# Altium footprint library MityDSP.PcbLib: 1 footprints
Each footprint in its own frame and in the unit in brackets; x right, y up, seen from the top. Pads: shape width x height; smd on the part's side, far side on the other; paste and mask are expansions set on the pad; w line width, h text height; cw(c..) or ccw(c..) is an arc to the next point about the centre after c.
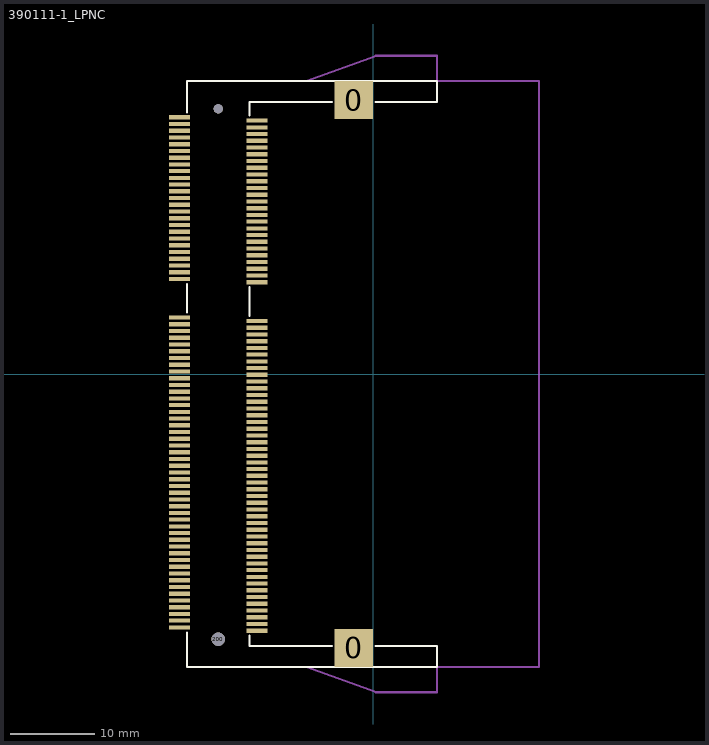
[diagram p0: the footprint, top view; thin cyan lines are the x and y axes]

## 390111-1_LPNC [mm] "MityDSP Socket No Clip"
height 5.6
pads (148):
  rect 4.6x4.5 smd: 0(-2.284,-32.55) 0(-2.284,32.55)
  rect 2.5x0.5 smd: 1(-22.981,30.5) 2(-13.781,30.1) 3(-22.981,29.7) 4(-13.781,29.3) 5(-22.981,28.9) 6(-13.781,28.5) 7(-22.981,28.1) 8(-13.781,27.7) 9(-22.981,27.3) 10(-13.781,26.9) 11(-22.981,26.5) 12(-13.781,26.1) 13(-22.981,25.7) 14(-13.781,25.3) 15(-22.981,24.9) 16(-13.781,24.5) 17(-22.981,24.1) 18(-13.781,23.7) 19(-22.981,23.3) 20(-13.781,22.9) 21(-22.981,22.5) 22(-13.781,22.1) 23(-22.981,21.7) 24(-13.781,21.3) 25(-22.981,20.9) 26(-13.781,20.5) 27(-22.981,20.1) 28(-13.781,19.7) 29(-22.981,19.3) 30(-13.781,18.9) 31(-22.981,18.5) 32(-13.781,18.1) 33(-22.981,17.7) 34(-13.781,17.3) 35(-22.981,16.9) 36(-13.781,16.5) 37(-22.981,16.1) 38(-13.781,15.7) 39(-22.981,15.3) 40(-13.781,14.9) 41(-22.981,14.5) 42(-13.781,14.1) 43(-22.981,13.7) 44(-13.781,13.3) 45(-22.981,12.9) 46(-13.781,12.5) 47(-22.981,12.1) 48(-13.781,11.7) 49(-22.981,11.3) 50(-13.781,10.9) 51(-22.981,6.7) 52(-13.781,6.3) 53(-22.981,5.9) 54(-13.781,5.5) 55(-22.981,5.1) 56(-13.781,4.7) 57(-22.981,4.3) 58(-13.781,3.9) 59(-22.981,3.5) 60(-13.781,3.1) 61(-22.981,2.7) 62(-13.781,2.3) 63(-22.981,1.9) 64(-13.781,1.5) 65(-22.981,1.1) 66(-13.781,0.7) 67(-22.981,0.3) 68(-13.781,-0.1) 69(-22.981,-0.5) 70(-13.781,-0.9) 71(-22.981,-1.3) 72(-13.781,-1.7) 73(-22.981,-2.1) 74(-13.781,-2.5) 75(-22.981,-2.9) 76(-13.781,-3.3) 77(-22.981,-3.7) 78(-13.781,-4.1) 79(-22.981,-4.5) 80(-13.781,-4.9) 81(-22.981,-5.3) 82(-13.781,-5.7) 83(-22.981,-6.1) 84(-13.781,-6.5) 85(-22.981,-6.9) 86(-13.781,-7.3) 87(-22.981,-7.7) 88(-13.781,-8.1) 89(-22.981,-8.5) 90(-13.781,-8.9) 91(-22.981,-9.3) 92(-13.781,-9.7) 93(-22.981,-10.1) 94(-13.781,-10.5) 95(-22.981,-10.9) 96(-13.781,-11.3) 97(-22.981,-11.7) 98(-13.781,-12.1) 99(-22.981,-12.5) 100(-13.781,-12.9) 101(-22.981,-13.3) 102(-13.781,-13.7) 103(-22.981,-14.1) 104(-13.781,-14.5) 105(-22.981,-14.9) 106(-13.781,-15.3) 107(-22.981,-15.7) 108(-13.781,-16.1) 109(-22.981,-16.5) 110(-13.781,-16.9) 111(-22.981,-17.3) 112(-13.781,-17.7) 113(-22.981,-18.1) 114(-13.781,-18.5) 115(-22.981,-18.9) 116(-13.781,-19.3) 117(-22.981,-19.7) 118(-13.781,-20.1) 119(-22.981,-20.5) 120(-13.781,-20.9) 121(-22.981,-21.3) 122(-13.781,-21.7) 123(-22.981,-22.1) 124(-13.781,-22.5) 125(-22.981,-22.9) 126(-13.781,-23.3) 127(-22.981,-23.7) 128(-13.781,-24.1) 129(-22.981,-24.5) 130(-13.781,-24.9) 131(-22.981,-25.3) 132(-13.781,-25.7) 133(-22.981,-26.1) 134(-13.781,-26.5) 135(-22.981,-26.9) 136(-13.781,-27.3) 137(-22.981,-27.7) 138(-13.781,-28.1) 139(-22.981,-28.5) 140(-13.781,-28.9) 141(-22.981,-29.3) 142(-13.781,-29.7) 143(-22.981,-30.1) 144(-13.781,-30.5)
  round 1.6 hole 1.6 unplated: 200(-18.384,-31.5)
  round 1.1 hole 1.1 unplated: 200(-18.384,31.5)
Top Overlay:
  lines w0.254: -22.084,-30.7 -22.084,-34.8 7.616,-34.8 7.616,-32.3 0.316,-32.3 ; -22.084,7.3 -22.084,10.7 ; -22.084,31.1 -22.084,34.8 7.616,34.8 7.616,32.3 0.316,32.3 ; -14.684,-31.1 -14.684,-32.3 -4.884,-32.3 ; -14.684,6.9 -14.684,10.3 ; -14.684,30.7 -14.684,32.3 -4.884,32.3
Mechanical 1:
  lines w0.254: 7.616,-34.8 19.716,-34.8 19.716,34.8 7.616,34.8 ; 7.616,-34.8 7.616,-37.8 0.33,-37.8 -7.884,-34.8 7.616,-34.8 ; 7.616,34.8 7.616,37.8 0.33,37.8 -7.884,34.8 7.616,34.8
3D body: height 5.6, standoff -0.7, extent -23.284,-34.85 6.616,34.85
